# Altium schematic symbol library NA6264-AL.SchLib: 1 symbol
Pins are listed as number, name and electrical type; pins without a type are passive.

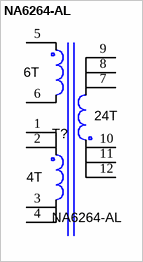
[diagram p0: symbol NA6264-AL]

## NA6264-AL
designator T?
COILCRAFT TRANSFORMER; Ns1toNp: 24;4; U/M: EA
footprint NA62XX-AL (COILCRAFT TRANFORMER)
pins: 1, 2, 3, 4, 5, 6, 7, 8, 9, 10, 11, 12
